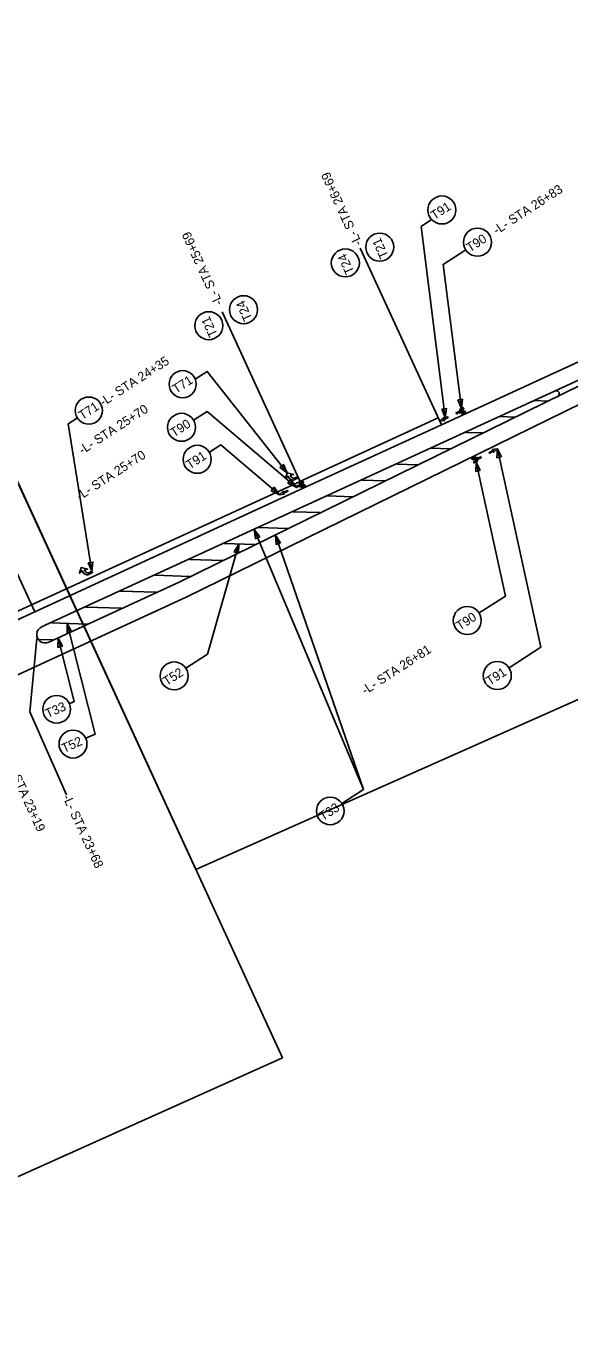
# Model space of a CAD drawing. Extents: x 553958 to 562499, y 493978 to 516388.
# Drawn here: x 555625 to 555983, y 503289 to 504146 of the extents above; entities that cross this region are included whole.
import ezdxf

# ---------------------------------------------------------------- set-up
doc = ezdxf.new("R2010")
doc.units = 0
for name, color, linetype in [('Prop Approach Slab', 7, 'Continuous'), ('Prop DSN Text', 7, 'Continuous'), ('Prop EOT', 7, 'Continuous'), ('Prop Erosion Rip Rap Class II Label', 7, 'Continuous'), ('Prop Horizontal Alignment', 7, 'Continuous'), ('Prop Horizontal Alignment Direction Label', 7, 'Continuous'), ('Prop Horizontal Alignment Tick Small', 7, 'Continuous'), ('Raster_Level_0', 7, 'Continuous'), ('Sheet Plan CELL', 7, 'Continuous'), ('Sheet Plot Border Inside CELL', 7, 'Continuous')]:
    doc.layers.add(name, color=color, linetype=linetype)

msp = doc.modelspace()

# ---------------------------------------------------------------- linework, layer by layer
at = {"layer": 'Prop Approach Slab'}
for p, q in [((555898.02, 503883.31), (555844.57, 503999.49)), ((555807.18, 503841.51), (555753.72, 503957.7)), ((555630.48, 503760.22), (555587.88, 503852.82)), ((555631.92, 503742.72), (555627.24, 503694.39)), ((555627.24, 503694.39), (555651.37, 503639.66))]:
    msp.add_line(p, q, dxfattribs=at)
at = {"layer": 'Prop EOT'}
for p, q in [((555805, 503846.01), (555895.93, 503887.85)), ((555807.18, 503841.51), (555898.02, 503883.31)), ((555557.65, 503732.22), (555628.39, 503764.76)), ((555559.74, 503727.68), (555630.48, 503760.22))]:
    msp.add_line(p, q, dxfattribs=at)
at = {"layer": 'Prop Erosion Rip Rap Class II Label'}
for points in [[(555736.45, 503590.64), (555435.27, 504245.31), (556565.58, 504822.05), (556936.88, 504379.27), (556608.88, 503978.75)], [(555793.48, 503466.69), (555600.74, 503885.63), (555438.59, 504238.1), (554125.45, 503648.45), (554482.04, 502854.33), (555335.17, 503260.89)]]:
    msp.add_lwpolyline(points, close=True, dxfattribs=at)
at = {"layer": 'Prop Horizontal Alignment'}
for p, q in [((555959.46, 503899.19), (555967.7, 503898.92)), ((555936.75, 503888.74), (555946.33, 503888.43)), ((555914.04, 503878.29), (555924.96, 503877.93)), ((555891.32, 503867.84), (555903.59, 503867.44)), ((555868.61, 503857.39), (555882.22, 503856.95)), ((555845.9, 503846.94), (555860.86, 503846.46)), ((555823.19, 503836.49), (555839.49, 503835.96)), ((555800.48, 503826.05), (555818.12, 503825.47)), ((555777.76, 503815.6), (555796.75, 503814.98)), ((555755.05, 503805.15), (555775.38, 503804.49)), ((555732.34, 503794.7), (555754.01, 503794)), ((555709.63, 503784.25), (555732.64, 503783.5)), ((555686.92, 503773.8), (555710.38, 503773.04)), ((555664.21, 503763.35), (555687.67, 503762.59)), ((555641.49, 503752.91), (555664.96, 503752.14)), ((555633.25, 503741.99), (555642.25, 503741.7))]:
    msp.add_line(p, q, dxfattribs=at)
at = {"layer": 'Prop Horizontal Alignment Direction Label'}
for points in [[(555803.62, 503849.23), (555804.04, 503848.32), (555801.69, 503847.25), (555801.25, 503847.07), (555800.9, 503846.98), (555800.48, 503846.93), (555800.11, 503846.94), (555799.81, 503847), (555799.39, 503847.12), (555799.09, 503847.25), (555798.75, 503847.43), (555798.37, 503847.68), (555798.12, 503847.92), (555797.83, 503848.25), (555797.51, 503848.75), (555797.18, 503849.48), (555795.42, 503847.93), (555796.58, 503851.59), (555800.87, 503850.63), (555798.62, 503850.14), (555798.9, 503849.54), (555799.07, 503849.2), (555799.3, 503848.93), (555799.53, 503848.74), (555799.86, 503848.51), (555800.13, 503848.37), (555800.54, 503848.27), (555800.96, 503848.26), (555801.37, 503848.28), (555801.88, 503848.43)], [(555803.62, 503849.23), (555804.04, 503848.32), (555801.69, 503847.25), (555801.25, 503847.07), (555800.9, 503846.98), (555800.48, 503846.93), (555800.11, 503846.94), (555799.81, 503847), (555799.39, 503847.12), (555799.09, 503847.25), (555798.75, 503847.43), (555798.37, 503847.68), (555798.12, 503847.92), (555797.83, 503848.25), (555797.51, 503848.75), (555797.18, 503849.48), (555795.42, 503847.93), (555796.58, 503851.59), (555800.87, 503850.63), (555798.62, 503850.14), (555798.9, 503849.54), (555799.07, 503849.2), (555799.3, 503848.93), (555799.53, 503848.74), (555799.86, 503848.51), (555800.13, 503848.37), (555800.54, 503848.27), (555800.96, 503848.26), (555801.37, 503848.28), (555801.88, 503848.43)], [(555668.17, 503786.92), (555668.59, 503786.01), (555666.24, 503784.93), (555665.8, 503784.75), (555665.44, 503784.66), (555665.03, 503784.61), (555664.66, 503784.63), (555664.36, 503784.68), (555663.94, 503784.8), (555663.63, 503784.94), (555663.29, 503785.11), (555662.91, 503785.37), (555662.67, 503785.6), (555662.37, 503785.94), (555662.06, 503786.43), (555661.72, 503787.16), (555659.96, 503785.62), (555661.12, 503789.27), (555665.42, 503788.31), (555663.16, 503787.83), (555663.44, 503787.22), (555663.62, 503786.89), (555663.85, 503786.61), (555664.07, 503786.42), (555664.4, 503786.19), (555664.68, 503786.06), (555665.09, 503785.95), (555665.51, 503785.94), (555665.91, 503785.97), (555666.43, 503786.12)], [(555668.17, 503786.92), (555668.59, 503786.01), (555666.24, 503784.93), (555665.8, 503784.75), (555665.44, 503784.66), (555665.03, 503784.61), (555664.66, 503784.63), (555664.36, 503784.68), (555663.94, 503784.8), (555663.63, 503784.94), (555663.29, 503785.11), (555662.91, 503785.37), (555662.67, 503785.6), (555662.37, 503785.94), (555662.06, 503786.43), (555661.72, 503787.16), (555659.96, 503785.62), (555661.12, 503789.27), (555665.42, 503788.31), (555663.16, 503787.83), (555663.44, 503787.22), (555663.62, 503786.89), (555663.85, 503786.61), (555664.07, 503786.42), (555664.4, 503786.19), (555664.68, 503786.06), (555665.09, 503785.95), (555665.51, 503785.94), (555665.91, 503785.97), (555666.43, 503786.12)]]:
    msp.add_lwpolyline(points, close=True, dxfattribs=at)
at = {"layer": 'Prop Horizontal Alignment Tick Small'}
for p, q in [((555908.1, 503891.44), (555908.03, 503891.58)), ((555908.1, 503891.44), (555908.03, 503891.58)), ((555908.53, 503890.56), (555908.46, 503890.7)), ((555908.53, 503890.56), (555908.46, 503890.7)), ((555908.64, 503891.55), (555910.09, 503892.37)), ((555908.86, 503891.31), (555908.64, 503891.55)), ((555910.15, 503890.95), (555908.86, 503891.31)), ((555910.05, 503892), (555909.11, 503891.46)), ((555909.11, 503891.46), (555910.43, 503891.08)), ((555910.82, 503891.33), (555910.05, 503892)), ((555910.09, 503892.37), (555912.19, 503892.62)), ((555910.43, 503891.08), (555910.15, 503890.95)), ((555912.22, 503892.38), (555910.24, 503892.15)), ((555910.24, 503892.15), (555910.83, 503891.64)), ((555911.48, 503891.85), (555910.82, 503891.33)), ((555910.83, 503891.64), (555911.34, 503892.04)), ((555911.17, 503894.13), (555911.28, 503893.91)), ((555911.17, 503894.13), (555911.28, 503893.91)), ((555911.34, 503892.04), (555911.48, 503891.85)), ((555911.64, 503893.18), (555911.74, 503892.96)), ((555911.64, 503893.18), (555911.74, 503892.96)), ((555912.19, 503892.62), (555912.24, 503892.38)), ((555912.25, 503891.93), (555912.35, 503891.71)), ((555912.25, 503891.93), (555912.35, 503891.71)), ((555912.71, 503890.98), (555912.82, 503890.76)), ((555912.71, 503890.98), (555912.82, 503890.76)), ((555919.24, 503861.76), (555919.13, 503861.98)), ((555919.24, 503861.76), (555919.13, 503861.98)), ((555919.74, 503860.83), (555919.62, 503861.04)), ((555919.74, 503860.83), (555919.62, 503861.04)), ((555919.81, 503860.15), (555919.75, 503860.37)), ((555919.78, 503860.38), (555921.75, 503860.67)), ((555921.9, 503860.45), (555919.81, 503860.15)), ((555920.38, 503859.6), (555920.27, 503859.81)), ((555920.38, 503859.6), (555920.27, 503859.81)), ((555920.5, 503860.93), (555921.14, 503861.47)), ((555920.65, 503860.75), (555920.5, 503860.93)), ((555921.15, 503861.16), (555920.65, 503860.75)), ((555920.87, 503858.66), (555920.76, 503858.88)), ((555920.87, 503858.66), (555920.76, 503858.88)), ((555921.14, 503861.47), (555921.93, 503860.83)), ((555921.75, 503860.67), (555921.15, 503861.16)), ((555921.52, 503861.73), (555921.8, 503861.87)), ((555922.86, 503861.39), (555921.52, 503861.73)), ((555921.8, 503861.87), (555923.1, 503861.55)), ((555923.33, 503861.31), (555921.9, 503860.45)), ((555921.93, 503860.83), (555922.86, 503861.39)), ((555923.1, 503861.55), (555923.33, 503861.31)), ((555923.41, 503862.3), (555923.48, 503862.17)), ((555923.41, 503862.3), (555923.48, 503862.17)), ((555923.86, 503861.44), (555923.94, 503861.31)), ((555923.86, 503861.44), (555923.94, 503861.31)), ((555802.71, 503842.95), (555802.64, 503843.08)), ((555802.71, 503842.95), (555802.64, 503843.08)), ((555803.14, 503842.07), (555803.07, 503842.21)), ((555803.14, 503842.07), (555803.07, 503842.21)), ((555803.25, 503843.06), (555804.7, 503843.88)), ((555803.47, 503842.82), (555803.25, 503843.06)), ((555804.76, 503842.46), (555803.47, 503842.82)), ((555804.67, 503843.51), (555803.72, 503842.97)), ((555803.72, 503842.97), (555805.04, 503842.59)), ((555805.43, 503842.84), (555804.67, 503843.51)), ((555804.7, 503843.88), (555806.8, 503844.12)), ((555805.04, 503842.59), (555804.76, 503842.46)), ((555806.83, 503843.89), (555804.85, 503843.66)), ((555804.85, 503843.66), (555805.44, 503843.15)), ((555806.09, 503843.36), (555805.43, 503842.84)), ((555805.44, 503843.15), (555805.95, 503843.55)), ((555805.78, 503845.64), (555805.89, 503845.42)), ((555805.78, 503845.64), (555805.89, 503845.42)), ((555805.95, 503843.55), (555806.09, 503843.36)), ((555806.25, 503844.69), (555806.36, 503844.47)), ((555806.25, 503844.69), (555806.36, 503844.47)), ((555806.8, 503844.12), (555806.86, 503843.89)), ((555806.86, 503843.44), (555806.96, 503843.22)), ((555806.86, 503843.44), (555806.96, 503843.22)), ((555807.32, 503842.49), (555807.43, 503842.27)), ((555807.32, 503842.49), (555807.43, 503842.27))]:
    msp.add_line(p, q, dxfattribs=at)
for points in [[(555900.24, 503886.23), (555899.37, 503886.59), (555902.46, 503888.02), (555902.19, 503888.6), (555899.11, 503887.17), (555899.4, 503888.07), (555896.88, 503885.79)], [(555900.24, 503886.23), (555899.37, 503886.59), (555902.46, 503888.02), (555902.19, 503888.6), (555899.11, 503887.17), (555899.4, 503888.07), (555896.88, 503885.79)], [(555931.5, 503866.97), (555932.38, 503866.65), (555929.36, 503865.09), (555929.65, 503864.53), (555932.68, 503866.08), (555932.43, 503865.18), (555934.84, 503867.55)], [(555931.5, 503866.97), (555932.38, 503866.65), (555929.36, 503865.09), (555929.65, 503864.53), (555932.68, 503866.08), (555932.43, 503865.18), (555934.84, 503867.55)], [(555794.85, 503837.74), (555793.99, 503838.1), (555797.07, 503839.53), (555796.8, 503840.11), (555793.72, 503838.68), (555794.01, 503839.58), (555791.49, 503837.3)], [(555794.85, 503837.74), (555793.99, 503838.1), (555797.07, 503839.53), (555796.8, 503840.11), (555793.72, 503838.68), (555794.01, 503839.58), (555791.49, 503837.3)]]:
    msp.add_lwpolyline(points, close=True, dxfattribs=at)
for centre, radius, start, end in [((555908.28, 503891.07), 0.563, 116.03765, 296.03765), ((555908.28, 503891.07), 0.563, 116.03765, 296.03765), ((555908.28, 503891.07), 0.41, 296.03765, 116.03765), ((555923.67, 503861.8), 0.41, 117.71087, 297.71087), ((555923.67, 503861.8), 0.563, 297.71087, 117.71087), ((555923.67, 503861.8), 0.563, 297.71087, 117.71087), ((555802.89, 503842.58), 0.563, 116.03765, 296.03765), ((555802.89, 503842.58), 0.563, 116.03765, 296.03765), ((555802.89, 503842.58), 0.41, 296.03765, 116.03765)]:
    msp.add_arc(centre, radius, start, end, dxfattribs=at)
for centre, major_axis, ratio, start_param, end_param in [((555911.46, 503893.54), (1.34, 0.66), 0.435841, 1.570796, 4.712389), ((555911.46, 503893.54), (1.12, 0.55), 0.325967, 1.570796, 4.712389), ((555912.53, 503891.35), (1.34, 0.66), 0.435841, 1.570796, 4.712389), ((555911.46, 503893.54), (1.34, 0.66), 0.435841, 4.712389, 7.853982), ((555911.46, 503893.54), (1.12, 0.55), 0.325967, 4.712389, 7.853982), ((555912.53, 503891.35), (1.12, 0.55), 0.325967, 1.570796, 4.712389), ((555912.53, 503891.35), (1.34, 0.66), 0.435841, 4.712389, 7.853982), ((555912.53, 503891.35), (1.12, 0.55), 0.325967, 4.712389, 7.853982), ((555919.43, 503861.4), (-1.32, -0.7), 0.435841, 4.712389, 7.853982), ((555919.43, 503861.4), (-1.11, -0.58), 0.325967, 4.712389, 7.853982), ((555919.43, 503861.4), (-1.32, -0.7), 0.435841, 1.570796, 4.712389), ((555920.57, 503859.24), (-1.32, -0.7), 0.435841, 4.712389, 7.853982), ((555919.43, 503861.4), (-1.11, -0.58), 0.325967, 1.570796, 4.712389), ((555920.57, 503859.24), (-1.11, -0.58), 0.325967, 4.712389, 7.853982), ((555920.57, 503859.24), (-1.32, -0.7), 0.435841, 1.570796, 4.712389), ((555920.57, 503859.24), (-1.11, -0.58), 0.325967, 1.570796, 4.712389), ((555806.07, 503845.05), (1.34, 0.66), 0.435841, 1.570796, 4.712389), ((555806.07, 503845.05), (1.12, 0.55), 0.325967, 1.570796, 4.712389), ((555807.14, 503842.86), (1.34, 0.66), 0.435841, 1.570796, 4.712389), ((555806.07, 503845.05), (1.34, 0.66), 0.435841, 4.712389, 7.853982), ((555806.07, 503845.05), (1.12, 0.55), 0.325967, 4.712389, 7.853982), ((555807.14, 503842.86), (1.12, 0.55), 0.325967, 1.570796, 4.712389), ((555807.14, 503842.86), (1.34, 0.66), 0.435841, 4.712389, 7.853982), ((555807.14, 503842.86), (1.12, 0.55), 0.325967, 4.712389, 7.853982)]:
    msp.add_ellipse(centre, major_axis=major_axis, ratio=ratio, start_param=start_param, end_param=end_param, dxfattribs=at)
at = {"layer": 'Raster_Level_0'}
for p, q in [((555635.07, 503750.23), (556116.75, 503971.82)), ((555725.52, 503779.73), (556116.75, 503971.82)), ((555725.52, 503779.73), (555639.69, 503740.24))]:
    msp.add_line(p, q, dxfattribs=at)
for centre, radius, start, end in [((555973.56, 503903.73), 2.02, 285.9338, 119.96072), ((555637.35, 503745.22), 5.5, 114.40117, 295.23567)]:
    msp.add_arc(centre, radius, start, end, dxfattribs=at)
at = {"layer": 'Sheet Plan CELL'}
for points in [[(555891.63, 504018.37), (555884.66, 504013.73), (555900.54, 503888.1)], [(555914.02, 503998.48), (555899.2, 503988.85), (555911.17, 503894.13)], [(555736.1, 503913.43), (555743.86, 503918.43), (555796.58, 503851.59)], [(555735.04, 503886.27), (555743.9, 503892.02), (555802.4, 503842.34)], [(555658.58, 503887.78), (555652.56, 503883.86), (555668.17, 503786.92)], [(555745.38, 503865.22), (555752.88, 503870.09), (555791.49, 503837.3)], [(555942.51, 503723.29), (555963.39, 503736.85), (555934.84, 503867.55)], [(555922.78, 503759.54), (555940.15, 503770.41), (555920.87, 503858.66)], [(555832.52, 503634.06), (555846.83, 503643.35), (555774.91, 503814.28)], [(555729.94, 503723.05), (555744.12, 503732.26), (555764.71, 503804.84)], [(555832.52, 503634.06), (555846.83, 503643.35), (555788.86, 503810.55)], [(555664.07, 503676.95), (555670.28, 503679.73), (555651.86, 503752.57)], [(555653.2, 503699.75), (555656.53, 503701.24), (555645.86, 503742.81)]]:
    msp.add_lwpolyline(points, dxfattribs=at)
for points in [[(555908.9, 503899.68), (555911.17, 503894.13), (555911.99, 503900.07)], [(555898.28, 503893.66), (555900.54, 503888.1), (555901.36, 503894.05)], [(555937.6, 503862.22), (555934.84, 503867.55), (555934.56, 503861.56)], [(555791.77, 503855.18), (555796.58, 503851.59), (555794.21, 503857.1)], [(555923.63, 503853.33), (555920.87, 503858.66), (555920.59, 503852.67)], [(555796.97, 503844.9), (555802.4, 503842.34), (555798.98, 503847.27)], [(555786.07, 503839.87), (555791.49, 503837.3), (555788.08, 503842.24)], [(555778.59, 503809.54), (555774.91, 503814.28), (555775.72, 503808.34)], [(555764.62, 503798.84), (555764.71, 503804.84), (555761.63, 503799.68)], [(555792.22, 503805.58), (555788.86, 503810.55), (555789.29, 503804.57)], [(555665.71, 503792.39), (555668.17, 503786.92), (555668.78, 503792.89)], [(555654.79, 503747.33), (555651.86, 503752.57), (555651.78, 503746.57)], [(555648.81, 503737.58), (555645.86, 503742.81), (555645.8, 503736.81)]]:
    msp.add_lwpolyline(points, close=True, dxfattribs=at)
for centre, radius in [((555898.35, 504024.69), 9.22), ((555857.47, 504000.26), 9.22), ((555921.75, 504003.5), 9.22), ((555834.84, 503989.85), 9.22), ((555767.89, 503959.05), 9.22), ((555745.02, 503948.53), 9.22), ((555727.84, 503910.02), 8.94), ((555666.08, 503892.65), 8.94), ((555727.08, 503881.66), 9.22), ((555737.4, 503860.6), 9.22), ((555915.05, 503754.52), 9.22), ((555722.23, 503718.04), 9.19), ((555934.79, 503718.27), 9.22), ((555644.94, 503696.04), 9.06), ((555655.68, 503673.18), 9.19), ((555824.92, 503629.12), 9.06)]:
    msp.add_circle(centre, radius, dxfattribs=at)
at = {"layer": 'Sheet Plot Border Inside CELL'}
for p, q in [((555898.02, 503883.31), (556137.13, 503993.31)), ((556121.24, 503961.78), (555730.17, 503769.76)), ((555628.39, 503764.76), (555805.09, 503846.05)), ((555630.48, 503760.22), (555807.18, 503841.51)), ((555657.31, 503736.24), (555730.23, 503769.79)), ((555503, 503665.25), (555657.31, 503736.24))]:
    msp.add_line(p, q, dxfattribs=at)

# ---------------------------------------------------------------- texts
at = {"layer": 'Prop DSN Text'}
msp.add_text('T24', height=6, rotation=114.70456, dxfattribs=at).set_placement((555840.84, 503983.99))
at = {"layer": 'Prop EOT'}
msp.add_text('T52', height=6, rotation=24.18158, dxfattribs=at).set_placement((555649.8, 503667.25))
at = {"layer": 'Sheet Plan CELL'}
for s, rotation, p in [('-L- STA 26+69', 114.70456, (555846.02, 504002.68)), ('-L- STA 26+83', 33.00067, (555934.48, 504008.29)), ('T91', 33.00067, (555893.42, 504017.91)), ('-L- STA 25+69', 114.70456, (555754.38, 503963.46)), ('T21', 114.70456, (555863.46, 503994.4)), ('T90', 33.00067, (555916.82, 503996.72)), ('T24', 114.70456, (555773.88, 503953.19)), ('T21', 114.70456, (555751.02, 503942.67)), ('-L- STA 24+35', 33.00067, (555675.64, 503895.28)), ('T71', 33.00067, (555723.53, 503903.65)), ('T71', 33.00067, (555661.78, 503886.28)), ('-L- STA 25+70', 33.00067, (555661.82, 503863.57)), ('T90', 33.00067, (555722.15, 503874.88)), ('-L- STA 25+70', 33.00067, (555660.17, 503833.41)), ('T91', 33.00067, (555732.47, 503853.82)), ('T90', 33.00067, (555910.12, 503747.74)), ('-L- STA 26+81', 33.00067, (555847.93, 503705.39)), ('T52', 33.00067, (555717.32, 503711.28)), ('T91', 33.00067, (555929.85, 503711.49)), ('T33', 24.18158, (555639.06, 503690.11)), ('-L- STA 23+19', 294.70456, (555610.51, 503662.45)), ('-L- STA 23+68', 294.70456, (555648.65, 503638.4)), ('T33', 33.00067, (555820.02, 503622.36))]:
    msp.add_text(s, height=6, rotation=rotation, dxfattribs=at).set_placement(p)

doc.saveas('drawing.dxf')
